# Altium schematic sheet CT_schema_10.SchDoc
size 254 x 194 mm
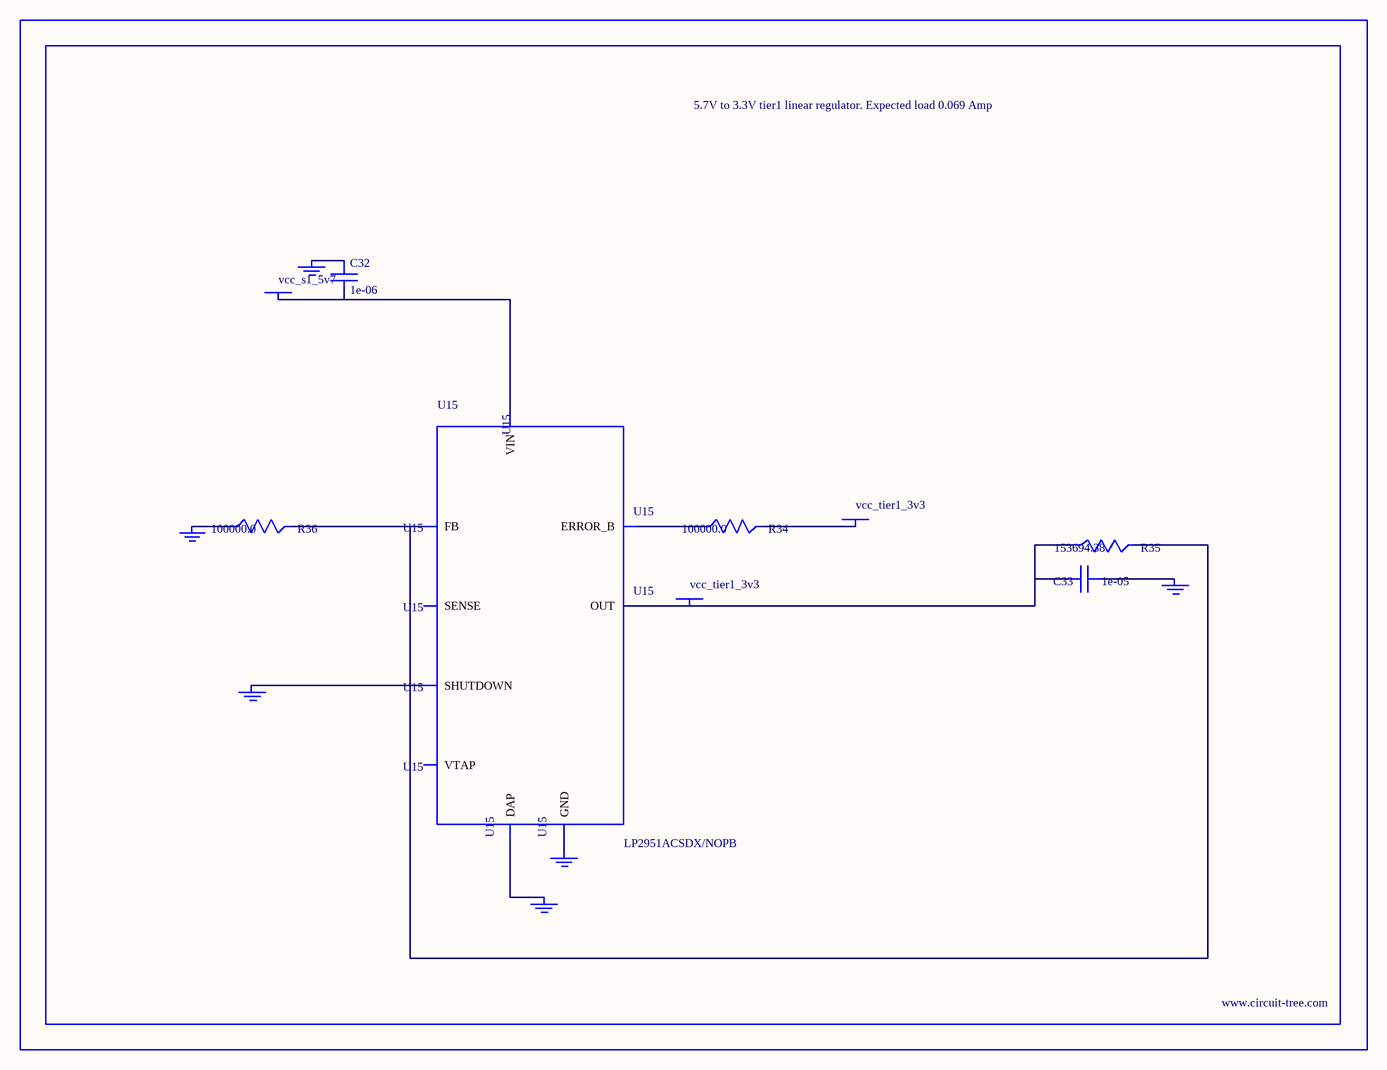
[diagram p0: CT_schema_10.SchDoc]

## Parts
BORDER9  (no value)
C32  1e-06  [C0603]
C33  1e-05  [C1210]
GND_INSTANCE_9_0  (no value)
GND_INSTANCE_9_1  (no value)
GND_INSTANCE_9_2  (no value)
GND_INSTANCE_9_3  (no value)
GND_INSTANCE_9_4  (no value)
GND_INSTANCE_9_5  (no value)
POWER_INSTANCE_9_0  vcc_tier1_3v3
POWER_INSTANCE_9_1  vcc_s1_5v7
POWER_INSTANCE_9_2  vcc_tier1_3v3
R34  100000.0  [R0603]
R35  153694.38  [R0603]
R36  100000.0  [R0603]
U15  LP2951ACSDX/NOPB  [WSON-8]

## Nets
NetC32_1: C32.1 GND_INSTANCE_9_3.0(GND)
NetC32_2: C32.2 POWER_INSTANCE_9_1.0(PWR) U15.8(VIN)
NetC33_1: C33.1 GND_INSTANCE_9_0.0(GND)
NetC33_2: C33.2 POWER_INSTANCE_9_2.0(PWR) R35.1 U15.1(OUT)
NetGND_INSTANCE_9_1_0: GND_INSTANCE_9_1.0(GND) U15.3(SHUTDOWN)
NetGND_INSTANCE_9_2_0: GND_INSTANCE_9_2.0(GND) R36.1
NetGND_INSTANCE_9_4_0: GND_INSTANCE_9_4.0(GND) U15.PAD(DAP)
NetGND_INSTANCE_9_5_0: GND_INSTANCE_9_5.0(GND) U15.4(GND)
NetPOWER_INSTANCE_9_0_0: POWER_INSTANCE_9_0.0(PWR) R34.2
NetR34_1: R34.1 U15.5(ERROR_B)
NetR35_2: R35.2 R36.2 U15.7(FB)

Not connected (* = marked no-connect by the designer): U15 2(SENSE) 6(VTAP)

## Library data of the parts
BORDER9 = BORDER_PAGE9
C32 = C0603C105K3RACTU
C33 = GRM32DR61E106MA12L
GND_INSTANCE_9_0-GND_INSTANCE_9_5 = GND
POWER_INSTANCE_9_0-POWER_INSTANCE_9_2 = PWR
R34 R36 = RC0603JR-07100KL
R35 = R35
